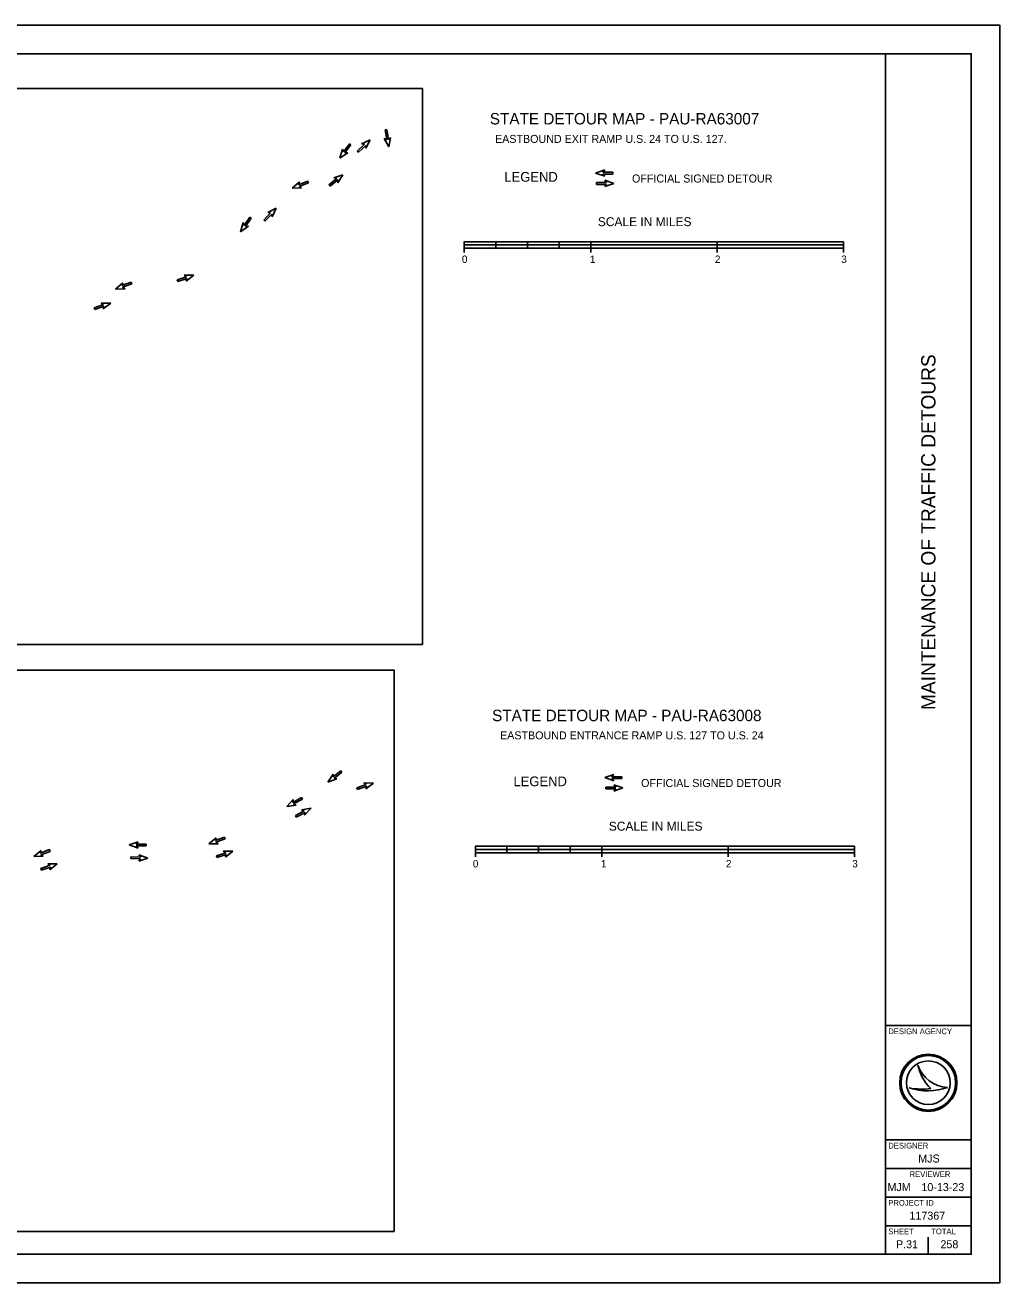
# Model space of a CAD drawing. Extents: x -8327 to 680, y -1188960 to 440.
# Drawn here: x 339.2 to 680, y 0 to 440 of the extents above; entities that cross this region are included whole.
import ezdxf

# ---------------------------------------------------------------- set-up
doc = ezdxf.new("R2010")
doc.units = 0
for name, color, linetype in [('GM_X_County', 7, 'Continuous'), ('GM_X_Minor_Lake', 7, 'Continuous'), ('GM_X_Minor_Lake_Text', 7, 'Continuous'), ('GM_X_Minor_River', 7, 'Continuous'), ('GM_X_Minor_River_Text', 7, 'Continuous')]:
    doc.layers.add(name, color=color, linetype=linetype)

msp = doc.modelspace()

# ---------------------------------------------------------------- linework, layer by layer
at = {"layer": 'GM_X_County'}
msp.add_lwpolyline([(0, 0), (680, 0), (680, 440), (0, 440)], close=True, dxfattribs=at)
at = {"layer": 'GM_X_Minor_Lake'}
for p, q in [((492.76, 364.21), (492.76, 360.48)), ((492.76, 361.97), (503.81, 361.97)), ((498.84, 364.21), (503.81, 364.21)), ((498.84, 363.09), (503.81, 363.09)), ((503.81, 364.21), (503.81, 361.97)), ((503.81, 364.21), (514.85, 364.21)), ((509.88, 363.09), (514.85, 363.09)), ((509.88, 361.97), (514.85, 361.97)), ((514.85, 364.21), (514.85, 361.97)), ((514.85, 361.97), (525.9, 361.97)), ((520.93, 364.21), (525.9, 364.21)), ((520.93, 363.09), (525.9, 363.09)), ((525.9, 364.21), (525.9, 361.97)), ((525.9, 364.21), (536.94, 364.21)), ((525.9, 363.09), (530.87, 363.09)), ((525.9, 361.97), (530.87, 361.97)), ((536.94, 360.48), (536.94, 364.21)), ((536.94, 361.97), (581.12, 361.97)), ((561.23, 364.21), (581.12, 364.21)), ((561.23, 363.09), (581.12, 363.09)), ((581.12, 360.48), (581.12, 364.21)), ((581.12, 364.21), (625.3, 364.21)), ((605.41, 363.09), (625.3, 363.09)), ((605.41, 361.97), (625.3, 361.97)), ((625.3, 360.48), (625.3, 364.21)), ((496.61, 152.73), (496.61, 149)), ((496.61, 150.49), (507.65, 150.49)), ((502.68, 152.73), (507.65, 152.73)), ((502.68, 151.61), (507.65, 151.61)), ((507.65, 152.73), (507.65, 150.49)), ((507.65, 152.73), (518.7, 152.73)), ((513.72, 151.61), (518.7, 151.61)), ((513.72, 150.49), (518.7, 150.49)), ((518.7, 152.73), (518.7, 150.49)), ((518.7, 150.49), (529.74, 150.49)), ((524.77, 152.73), (529.74, 152.73)), ((524.77, 151.61), (529.74, 151.61)), ((529.74, 152.73), (529.74, 150.49)), ((529.74, 152.73), (540.79, 152.73)), ((529.74, 151.61), (534.72, 151.61)), ((529.74, 150.49), (534.72, 150.49)), ((540.79, 149), (540.79, 152.73)), ((540.79, 150.49), (584.97, 150.49)), ((565.07, 152.73), (584.97, 152.73)), ((565.07, 151.61), (584.97, 151.61)), ((584.97, 149), (584.97, 152.73)), ((584.97, 152.73), (629.15, 152.73)), ((609.25, 151.61), (629.15, 151.61)), ((609.25, 150.49), (629.15, 150.49)), ((629.15, 149), (629.15, 152.73))]:
    msp.add_line(p, q, dxfattribs=at)
for points in [[(58.11, 417.89), (478.11, 417.89), (478.11, 223.38), (58.11, 223.38)], [(503.81, 363.09), (492.76, 363.09), (492.76, 364.21), (503.81, 364.21)], [(503.81, 363.09), (514.85, 363.09), (514.85, 361.97), (503.81, 361.97)], [(514.85, 363.09), (525.9, 363.09), (525.9, 364.21), (514.85, 364.21)], [(525.9, 363.09), (536.94, 363.09), (536.94, 361.97), (525.9, 361.97)], [(536.94, 363.09), (581.12, 363.09), (581.12, 364.21), (536.94, 364.21)], [(581.12, 363.09), (625.3, 363.09), (625.3, 361.97), (581.12, 361.97)], [(58.11, 214.39), (468.2, 214.39), (468.2, 18), (58.11, 18)], [(507.65, 151.61), (496.61, 151.61), (496.61, 152.73), (507.65, 152.73)], [(507.65, 151.61), (518.7, 151.61), (518.7, 150.49), (507.65, 150.49)], [(518.7, 151.61), (529.74, 151.61), (529.74, 152.73), (518.7, 152.73)], [(529.74, 151.61), (540.79, 151.61), (540.79, 150.49), (529.74, 150.49)], [(540.79, 151.61), (584.97, 151.61), (584.97, 152.73), (540.79, 152.73)], [(584.96, 151.61), (629.15, 151.61), (629.15, 150.49), (584.96, 150.49)]]:
    msp.add_lwpolyline(points, close=True, dxfattribs=at)
at = {"layer": 'GM_X_Minor_Lake_Text'}
for p, q in [((651.35, 76.19), (651.35, 76.19)), ((648.34, 68.19), (648.34, 68.19)), ((655, 70), (655, 70)), ((661.75, 68.37), (661.75, 68.37)), ((647.5, 13.5), (647.5, 13.5)), ((655, 10), (655, 16))]:
    msp.add_line(p, q, dxfattribs=at)
for radius in [10, 9.54, 9.54, 7.64]:
    msp.add_circle((655, 70), radius, dxfattribs=at)
for centre, radius, start, end in [((662.32, 79.95), 11.6, 198.9257, 198.9319), ((666.93, 79.4), 15.91, 191.6379, 191.6421), ((662.32, 79.95), 11.6, 198.9319, 267.1657), ((666.93, 79.4), 15.91, 191.6421, 226.0947), ((654.79, 87.4), 20.26, 251.4576, 290.0832), ((652.96, 93.09), 25.32, 259.4964, 259.4995), ((654.79, 87.4), 20.26, 251.4527, 251.4576), ((652.96, 93.09), 25.32, 259.4995, 276.6672)]:
    msp.add_arc(centre, radius, start, end, dxfattribs=at)
at = {"layer": 'GM_X_Minor_River'}
for p, q in [((465.07, 403.32), (465.69, 403.43)), ((465.63, 399.89), (465.07, 403.32)), ((465.69, 403.43), (466.25, 399.99)), ((466.25, 399.99), (466.92, 400.74)), ((466.92, 400.74), (466.35, 397.44)), ((449.2, 393.46), (450.22, 396.65)), ((450.22, 396.65), (450.47, 395.68)), ((450.47, 395.68), (452.56, 398.46)), ((453.06, 398.08), (450.97, 395.3)), ((452.56, 398.46), (453.06, 398.08)), ((455.34, 395.96), (457.83, 398.39)), ((458.27, 397.94), (455.78, 395.51)), ((456.83, 398.51), (459.87, 399.93)), ((457.83, 398.39), (456.83, 398.51)), ((458.37, 396.94), (458.27, 397.94)), ((459.87, 399.93), (458.37, 396.94)), ((466.35, 397.44), (464.75, 400.39)), ((464.75, 400.39), (465.63, 399.89)), ((451.98, 395.33), (449.2, 393.46)), ((450.97, 395.3), (451.98, 395.33)), ((455.78, 395.51), (455.34, 395.96)), ((447.16, 386.53), (450.31, 387.66)), ((450.31, 387.66), (448.53, 384.82)), ((538.66, 388.23), (541.83, 389.33)), ((541.83, 387.14), (538.66, 388.23)), ((541.83, 389.33), (541.2, 388.55)), ((541.2, 388.55), (544.68, 388.55)), ((544.68, 387.92), (541.2, 387.92)), ((541.2, 387.92), (541.83, 387.14)), ((544.68, 388.55), (544.68, 387.92)), ((432.52, 382.97), (435.07, 385.14)), ((435.86, 383.09), (432.52, 382.97)), ((434.76, 384.18), (438, 385.44)), ((435.07, 385.14), (434.76, 384.18)), ((438.23, 384.85), (434.99, 383.59)), ((434.99, 383.59), (435.86, 383.09)), ((438, 385.44), (438.23, 384.85)), ((445.43, 384.14), (448.14, 386.32)), ((445.82, 383.65), (445.43, 384.14)), ((448.54, 385.83), (445.82, 383.65)), ((448.14, 386.32), (447.16, 386.53)), ((448.53, 384.82), (448.54, 385.83)), ((539.03, 384.31), (539.03, 384.94)), ((539.03, 384.94), (542.51, 384.94)), ((542.51, 384.31), (539.03, 384.31)), ((542.51, 384.94), (541.88, 385.72)), ((541.88, 385.72), (545.04, 384.63)), ((545.04, 384.63), (541.88, 383.53)), ((541.88, 383.53), (542.51, 384.31)), ((422.61, 371.83), (425.02, 374.34)), ((424.02, 374.43), (427.01, 375.94)), ((425.02, 374.34), (424.02, 374.43)), ((427.01, 375.94), (425.6, 372.9)), ((414.53, 367.71), (415.45, 370.93)), ((417.25, 369.67), (414.53, 367.71)), ((415.45, 370.93), (415.73, 369.96)), ((415.73, 369.96), (417.73, 372.81)), ((418.25, 372.45), (416.24, 369.6)), ((416.24, 369.6), (417.25, 369.67)), ((417.73, 372.81), (418.25, 372.45)), ((423.06, 371.39), (422.61, 371.83)), ((425.48, 373.9), (423.06, 371.39)), ((425.6, 372.9), (425.48, 373.9)), ((395.63, 351.98), (394.78, 352.52)), ((394.78, 352.52), (398.13, 352.5)), ((398.13, 352.5), (395.49, 350.44)), ((370.8, 347.68), (373.37, 349.82)), ((374.14, 347.77), (370.8, 347.68)), ((373.05, 348.87), (376.31, 350.09)), ((373.37, 349.82), (373.05, 348.87)), ((376.54, 349.5), (373.28, 348.28)), ((373.28, 348.28), (374.14, 347.77)), ((376.31, 350.09), (376.54, 349.5)), ((392.34, 350.86), (395.63, 351.98)), ((392.54, 350.26), (392.34, 350.86)), ((395.84, 351.38), (392.54, 350.26)), ((395.49, 350.44), (395.84, 351.38)), ((363.35, 341.14), (366.64, 342.26)), ((363.55, 340.54), (363.35, 341.14)), ((366.85, 341.66), (363.55, 340.54)), ((366.64, 342.26), (365.79, 342.79)), ((365.79, 342.79), (369.14, 342.78)), ((369.14, 342.78), (366.5, 340.71)), ((366.5, 340.71), (366.85, 341.66)), ((445.08, 175.15), (446.85, 177.99)), ((448.23, 176.27), (445.08, 175.15)), ((446.85, 176.98), (449.56, 179.16)), ((446.85, 177.99), (446.85, 176.98)), ((449.96, 178.67), (447.25, 176.49)), ((447.25, 176.49), (448.23, 176.27)), ((449.56, 179.16), (449.96, 178.67)), ((541.84, 176.75), (545, 177.84)), ((545, 175.65), (541.84, 176.75)), ((545, 177.84), (544.37, 177.06)), ((544.37, 177.06), (547.85, 177.06)), ((547.85, 176.43), (544.37, 176.43)), ((544.37, 176.43), (545, 175.65)), ((547.85, 177.06), (547.85, 176.43)), ((455.19, 173.22), (458.48, 174.34)), ((455.39, 172.62), (455.19, 173.22)), ((458.69, 173.74), (455.39, 172.62)), ((458.48, 174.34), (457.63, 174.88)), ((457.63, 174.88), (460.98, 174.85)), ((460.98, 174.85), (458.34, 172.79)), ((458.34, 172.79), (458.69, 173.74)), ((542.2, 172.82), (542.2, 173.45)), ((542.2, 173.45), (545.68, 173.45)), ((545.68, 172.82), (542.2, 172.82)), ((545.68, 173.45), (545.05, 174.24)), ((545.05, 174.24), (548.22, 173.14)), ((548.22, 173.14), (545.05, 172.04)), ((545.05, 172.04), (545.68, 172.82)), ((430.7, 166.63), (432.97, 169.09)), ((432.78, 168.1), (435.85, 169.75)), ((432.97, 169.09), (432.78, 168.1)), ((436.15, 169.2), (433.08, 167.55)), ((433.08, 167.55), (434.01, 167.16)), ((435.85, 169.75), (436.15, 169.2)), ((434.01, 167.16), (430.7, 166.63)), ((433.7, 163.48), (436.77, 165.12)), ((434, 162.92), (433.7, 163.48)), ((437.07, 164.56), (434, 162.92)), ((435.84, 165.51), (439.15, 166.03)), ((436.77, 165.12), (435.84, 165.51)), ((439.15, 166.03), (436.88, 163.57)), ((436.88, 163.57), (437.07, 164.56)), ((375.53, 153.19), (378.69, 154.28)), ((378.69, 154.28), (378.06, 153.5)), ((403.37, 153.54), (405.95, 155.68)), ((405.63, 154.72), (408.89, 155.94)), ((405.95, 155.68), (405.63, 154.72)), ((409.11, 155.35), (405.85, 154.13)), ((405.85, 154.13), (406.72, 153.62)), ((408.89, 155.94), (409.11, 155.35)), ((342.19, 149.14), (344.77, 151.28)), ((344.45, 150.32), (347.71, 151.55)), ((344.77, 151.28), (344.45, 150.32)), ((347.93, 150.95), (344.67, 149.73)), ((344.67, 149.73), (345.54, 149.22)), ((347.71, 151.55), (347.93, 150.95)), ((378.69, 152.08), (375.53, 153.19)), ((378.06, 153.5), (381.54, 153.49)), ((381.54, 152.86), (378.06, 152.87)), ((378.06, 152.87), (378.69, 152.08)), ((379.61, 148.97), (378.99, 149.77)), ((378.99, 149.77), (382.13, 148.61)), ((381.54, 153.49), (381.54, 152.86)), ((406.72, 153.62), (403.37, 153.54)), ((406.05, 149.37), (409.34, 150.49)), ((409.55, 149.89), (406.25, 148.77)), ((409.34, 150.49), (408.49, 151.02)), ((408.49, 151.02), (411.84, 151)), ((411.84, 151), (409.2, 148.94)), ((409.2, 148.94), (409.55, 149.89)), ((345.54, 149.22), (342.19, 149.14)), ((344.64, 144.96), (347.94, 146.08)), ((348.14, 145.48), (344.85, 144.36)), ((347.94, 146.08), (347.09, 146.62)), ((347.09, 146.62), (350.44, 146.59)), ((350.44, 146.59), (347.79, 144.54)), ((347.79, 144.54), (348.14, 145.48)), ((376.11, 148.41), (376.13, 149.04)), ((379.59, 148.34), (376.11, 148.41)), ((376.13, 149.04), (379.61, 148.97)), ((382.13, 148.61), (378.95, 147.57)), ((378.95, 147.57), (379.59, 148.34)), ((406.25, 148.77), (406.05, 149.37)), ((344.85, 144.36), (344.64, 144.96))]:
    msp.add_line(p, q, dxfattribs=at)
at = {"layer": 'GM_X_Minor_River_Text'}
for p, q in [((640, 10), (640, 430)), ((640, 90), (670, 90)), ((640, 50), (670, 50)), ((640, 40), (670, 40)), ((640, 30), (670, 30)), ((640, 20), (670, 20))]:
    msp.add_line(p, q, dxfattribs=at)
msp.add_lwpolyline([(30, 430), (670, 430), (670, 10), (30, 10)], close=True, dxfattribs=at)

# ---------------------------------------------------------------- texts
at = {"layer": 'GM_X_Minor_Lake'}
for s, height, p in [('EASTBOUND EXIT RAMP U.S. 24 TO U.S. 127.', 2.8, (503.5, 398.8)), ('SCALE IN MILES', 3.125, (539.45, 369.68)), ('0', 2.6, (491.91, 356.81)), ('1', 2.6, (536.65, 356.81)), ('2', 2.6, (580.38, 356.81)), ('3', 2.6, (624.56, 356.81)), ('EASTBOUND ENTRANCE RAMP U.S. 127 TO U.S. 24 ', 2.8, (505.25, 190.14)), ('SCALE IN MILES', 3.125, (543.29, 158.2)), ('0', 2.6, (495.75, 145.33)), ('1', 2.6, (540.5, 145.33)), ('2', 2.6, (584.22, 145.33)), ('3', 2.6, (628.41, 145.33))]:
    msp.add_text(s, height=height, dxfattribs=at).set_placement(p)
at = {"layer": 'GM_X_Minor_Lake_Text'}
for s, height, p in [('STATE DETOUR MAP - PAU-RA63007', 4, (501.67, 405.27)), ('LEGEND', 3.4, (506.75, 385.23)), ('OFFICIAL SIGNED DETOUR', 2.8, (551.4, 384.95)), ('STATE DETOUR MAP - PAU-RA63008', 4, (502.46, 196.5)), ('LEGEND', 3.4, (509.93, 173.74)), ('OFFICIAL SIGNED DETOUR', 2.8, (554.57, 173.46)), ('DESIGN AGENCY', 2, (641, 87)), ('DESIGNER', 2, (641, 47)), ('MJS', 2.8, (651.48, 42.1)), ('REVIEWER', 2, (648.44, 37)), ('MJM', 2.8, (640.71, 32.1)), ('10-13-23', 2.8, (652.58, 32.1)), ('PROJECT ID', 2, (641, 27)), ('117367', 2.8, (648.4, 22.1)), ('SHEET', 2, (641, 17)), ('TOTAL', 2, (656, 17)), ('P.31', 2.8, (643.69, 12.1)), ('258', 2.8, (659.24, 12.1))]:
    msp.add_text(s, height=height, dxfattribs=at).set_placement(p)
msp.add_text('MAINTENANCE OF TRAFFIC DETOURS', height=5, rotation=90, dxfattribs=at).set_placement((657.5, 200.41))

doc.saveas('drawing.dxf')
